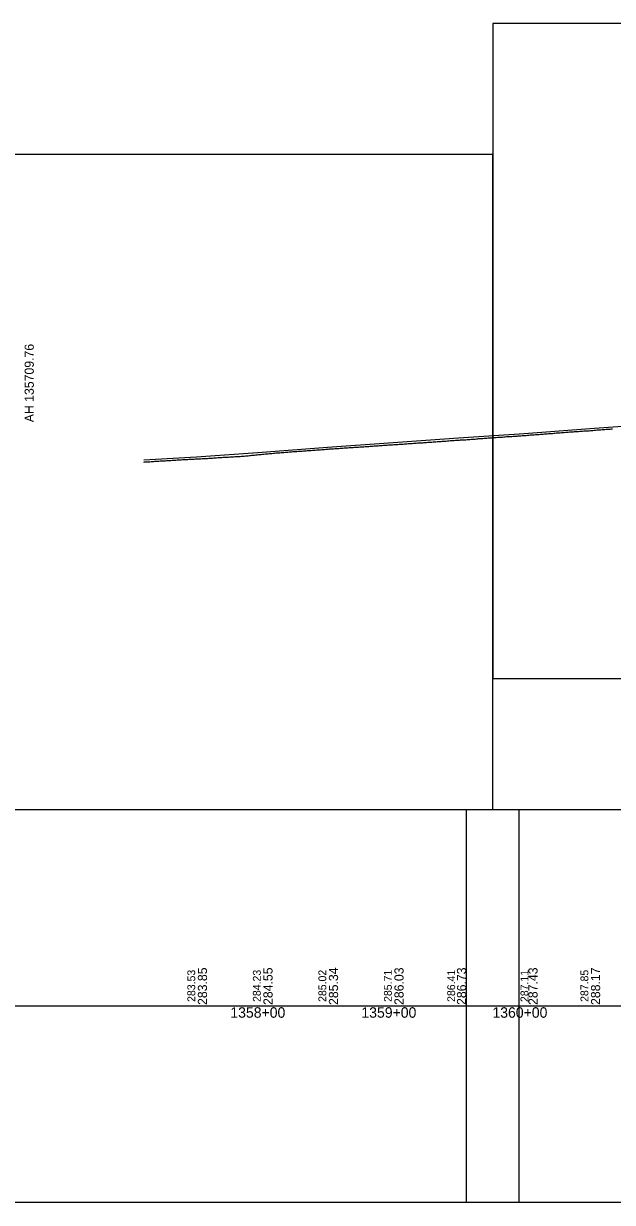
# Model space of a CAD drawing. Extents: x -3627 to 47473, y 2850 to 4350.
# Drawn here: x 23095 to 23545, y 2850 to 3750 of the extents above; entities that cross this region are included whole.
import ezdxf

# ---------------------------------------------------------------- set-up
doc = ezdxf.new("R2010")
doc.units = 0
for name, color, linetype in [('RD_DDB_Profile_EX', 7, 'Continuous'), ('RD_DDB_Profile_PR', 7, 'Continuous'), ('RD_DDB_StaTX', 7, 'Continuous'), ('RD_DDB_StripGrade', 7, 'Continuous'), ('RD_GPK_Profile_Cell', 7, 'Continuous'), ('RD_SHT_ShtClip', 7, 'Continuous')]:
    doc.layers.add(name, color=color, linetype=linetype)

msp = doc.modelspace()

# ---------------------------------------------------------------- linework, layer by layer
at = {"layer": 'RD_DDB_Profile_EX'}
for points in [[(23486.870699, 3436.29383), (23487.872155, 3436.33528), (23488.871967, 3436.376475), (23489.866682, 3436.46569), (23490.872592, 3436.56458), (23491.873491, 3436.605095), (23492.86821, 3436.66492), (23493.869666, 3436.756335), (23494.869485, 3436.807275), (23495.870948, 3436.918235), (23496.871194, 3436.97517), (23497.87265, 3437.09588), (23498.872472, 3437.146695), (23499.867176, 3437.23695), (23500.868632, 3437.328365), (23501.868467, 3437.43892), (23502.864233, 3437.44808), (23503.87016, 3437.537355), (23504.86999, 3437.628505), (23505.864687, 3437.6785), (23506.866143, 3437.720005), (23507.867051, 3437.837865), (23508.86851, 3437.979175), (23509.867671, 3438.03701), (23510.867508, 3438.02805), (23511.868972, 3438.202135), (23512.863653, 3438.211735), (23513.865109, 3438.32995), (23514.866565, 3438.430905), (23515.864115, 3438.459595), (23516.865575, 3438.539355), (23517.867036, 3438.590265), (23518.861705, 3438.690255), (23519.867648, 3438.789405), (23520.867505, 3438.792395), (23521.862175, 3438.811465), (23522.867055, 3438.970535), (23523.861729, 3439.010965), (23524.867662, 3438.97921), (23525.869127, 3439.141915), (23526.862195, 3439.19164), (23527.868123, 3439.309825), (23528.862804, 3439.369425), (23529.864267, 3439.41084), (23530.870198, 3439.55791), (23531.864879, 3439.5983), (23532.864732, 3439.739375), (23533.86281, 3439.77842), (23534.86428, 3439.860165), (23535.865749, 3439.91118), (23536.864887, 3439.98811), (23537.864741, 3440.088785), (23538.859421, 3440.14838), (23539.865344, 3440.257225), (23540.866815, 3440.308035), (23541.865951, 3440.41615), (23542.86742, 3440.466915), (23543.860487, 3440.516725), (23544.865339, 3440.56637)], [(23286.89401, 3422.11666), (23287.896593, 3422.19705), (23288.900758, 3422.26593), (23289.89553, 3422.32608), (23290.902513, 3422.374555), (23291.89558, 3422.464075), (23292.901433, 3422.543795), (23293.895631, 3422.653325), (23294.8971, 3422.7543), (23295.897418, 3422.791645), (23296.89715, 3422.8924), (23297.902993, 3423.00183), (23298.897201, 3423.06148), (23299.903036, 3423.13983), (23300.897852, 3423.179435), (23301.89872, 3423.269295), (23302.897906, 3423.31724), (23303.898771, 3423.3675), (23304.89796, 3423.444375), (23305.897662, 3423.55575), (23306.898015, 3423.563665), (23307.899482, 3423.67532), (23308.903514, 3423.70289), (23309.899536, 3423.762965), (23310.899222, 3423.87437), (23311.89959, 3424.00048), (23312.901057, 3424.05161), (23313.898458, 3424.12772), (23314.901111, 3424.189035), (23315.898505, 3424.236545), (23316.901165, 3424.28711), (23317.902632, 3424.366785), (23318.900023, 3424.44663), (23319.902686, 3424.49718), (23320.90007, 3424.63388), (23321.901542, 3424.67419), (23322.900117, 3424.720995), (23323.901589, 3424.772205), (23324.895862, 3424.9151), (23325.902849, 3425.002625), (23326.895916, 3425.052355), (23327.902903, 3425.184075), (23328.903732, 3425.26212), (23329.901083, 3425.3099), (23330.903783, 3425.349255), (23331.898082, 3425.398395), (23332.905071, 3425.49687), (23333.898139, 3425.5466), (23334.905129, 3425.58378), (23335.899448, 3425.671555), (23336.903277, 3425.747475), (23337.905999, 3425.809405), (23338.904586, 3425.89472), (23339.907316, 3426.029615), (23340.900385, 3426.10643), (23341.905443, 3426.100455), (23342.901723, 3426.215285), (23343.905493, 3426.302365), (23344.901791, 3426.340125), (23345.902589, 3426.401925), (23346.903387, 3426.4601), (23347.90485, 3426.54957), (23348.8992, 3426.57554), (23349.90194, 3426.614485), (23350.902739, 3426.714675), (23351.906506, 3426.76332), (23352.902811, 3426.801075), (23353.903607, 3426.901265), (23354.905065, 3426.952515), (23355.905864, 3427.014285), (23356.900218, 3427.063315), (23357.901674, 3427.11453), (23358.90313, 3427.177265), (23359.904587, 3427.26695), (23360.897657, 3427.31665), (23361.899113, 3427.417865), (23362.900569, 3427.519075), (23363.906301, 3427.568055), (23364.901291, 3427.66388), (23365.900831, 3427.741795), (23366.902292, 3427.804295), (23367.89727, 3427.88159), (23368.898723, 3427.932755), (23369.898283, 3428.033595), (23370.899743, 3428.08476), (23371.894702, 3428.1848), (23372.896156, 3428.197185), (23373.895734, 3428.275625), (23374.897195, 3428.36569), (23375.896439, 3428.41341), (23376.899139, 3428.51399), (23377.89872, 3428.56489), (23378.900181, 3428.643885), (23379.895117, 3428.66618), (23380.896571, 3428.76743), (23381.896171, 3428.796225), (23382.897632, 3428.886545), (23383.892549, 3428.914555), (23384.894003, 3429.0099), (23385.893623, 3429.0999), (23386.895084, 3429.151235)], [(23386.895084, 3429.151235), (23387.894314, 3429.21585), (23388.895773, 3429.30011), (23389.897231, 3429.35144), (23390.892535, 3429.404905), (23391.893996, 3429.484755), (23392.888868, 3429.613305), (23393.890321, 3429.686205), (23394.889986, 3429.74791), (23395.891447, 3429.78866), (23396.892908, 3429.85832), (23397.889993, 3429.91511), (23398.890295, 3429.977515), (23399.88511, 3430.037935), (23400.886564, 3430.089185), (23401.886286, 3430.18846), (23402.887746, 3430.25021), (23403.888075, 3430.30232), (23404.889541, 3430.35466), (23405.879898, 3430.43676), (23406.881352, 3430.548115), (23407.881696, 3430.60996), (23408.883154, 3430.67113), (23409.884612, 3430.68262), (23410.886071, 3430.833335), (23411.884792, 3430.90523), (23412.87951, 3430.995405), (23413.876517, 3431.018575), (23414.877975, 3431.079445), (23415.879434, 3431.142125), (23416.879833, 3431.203625), (23417.881296, 3431.29299), (23418.875963, 3431.412015), (23419.877419, 3431.53201), (23420.87783, 3431.614555), (23421.873224, 3431.667365), (23422.874687, 3431.759135), (23423.87615, 3431.810215), (23424.877613, 3431.829655), (23425.871207, 3431.911745), (23426.872668, 3432.0037), (23427.874128, 3432.05482), (23428.875589, 3432.087855), (23429.871515, 3432.141925), (23430.871487, 3432.24286), (23431.872955, 3432.29406), (23432.867505, 3432.326375), (23433.868462, 3432.38565), (23434.86757, 3432.442065), (23435.868523, 3432.560245), (23436.874529, 3432.618085), (23437.870084, 3432.62654), (23438.874582, 3432.748345), (23439.870156, 3432.788815), (23440.874635, 3432.878335), (23441.870229, 3432.99592), (23442.870168, 3433.10586), (23443.870301, 3433.15316), (23444.870229, 3433.213135), (23445.870373, 3433.269745), (23446.870289, 3433.361365), (23447.877282, 3433.45063), (23448.87035, 3433.5596), (23449.872833, 3433.6102), (23450.870411, 3433.70783), (23451.871874, 3433.75891), (23452.872045, 3433.815685), (23453.871935, 3433.93846), (23454.872117, 3433.99511), (23455.871995, 3434.0836), (23456.872189, 3434.1718), (23457.872056, 3434.203605), (23458.874564, 3434.204195), (23459.872117, 3434.31138), (23460.874633, 3434.32386), (23461.872177, 3434.478905), (23462.874701, 3434.560245), (23463.872238, 3434.62894), (23464.874769, 3434.6682), (23465.867839, 3434.738945), (23466.874837, 3434.79711), (23467.867907, 3434.85658), (23468.873822, 3434.895845), (23469.876364, 3434.986665), (23470.873883, 3435.113765), (23471.876432, 3435.075005), (23472.873944, 3435.162575), (23473.875407, 3435.29339), (23474.870132, 3435.373645), (23475.874371, 3435.39254), (23476.870205, 3435.50187), (23477.871661, 3435.5927), (23478.877561, 3435.61191), (23479.87063, 3435.721555), (23480.87209, 3435.84252), (23481.874645, 3435.933205), (23482.874449, 3435.98405), (23483.869171, 3436.0045), (23484.875076, 3436.08358), (23485.874883, 3436.224005), (23486.870699, 3436.29383)], [(23187.09, 3415.259485), (23187.600115, 3415.300215), (23188.595764, 3415.3496), (23189.601713, 3415.37409), (23190.595953, 3415.45539), (23191.603332, 3415.5215), (23192.596469, 3415.6122), (23193.60239, 3415.710105), (23194.604698, 3415.769875), (23195.604025, 3415.857415), (23196.604872, 3415.86698), (23197.605681, 3415.90472), (23198.605383, 3415.974115), (23199.604707, 3416.06159), (23200.607043, 3416.05301), (23201.60638, 3416.05896), (23202.607216, 3416.20936), (23203.608074, 3416.275265), (23204.607733, 3416.357285), (23205.608602, 3416.40424), (23206.609431, 3416.45463), (23207.610262, 3416.514535), (23208.61115, 3416.59235), (23209.611976, 3416.65235), (23210.610126, 3416.66081), (23211.612507, 3416.751915), (23212.611863, 3416.887115), (23213.612683, 3416.94726), (23214.61362, 3416.9942), (23215.614436, 3417.024855), (23216.612563, 3417.09179), (23217.614973, 3417.13254), (23218.614338, 3417.149105), (23219.615148, 3417.199445), (23220.622543, 3417.25779), (23221.61694, 3417.336695), (23222.621446, 3417.385205), (23223.617484, 3417.42441), (23224.618652, 3417.50614), (23225.616752, 3417.55355), (23226.617926, 3417.59457), (23227.6191, 3417.675535), (23228.613869, 3417.74582), (23229.618367, 3417.79438), (23230.619546, 3417.80577), (23231.615582, 3417.84503), (23232.616749, 3417.89627), (23233.621251, 3417.88466), (23234.616025, 3417.964325), (23235.617198, 3418.07582), (23236.61837, 3418.17714), (23237.616468, 3418.20483), (23238.617645, 3418.24589), (23239.618822, 3418.326935), (23240.613584, 3418.416845), (23241.613139, 3418.46819), (23242.619273, 3418.51714), (23243.614036, 3418.59694), (23244.615212, 3418.658235), (23245.614776, 3418.70913), (23246.614487, 3418.75686), (23247.616919, 3418.857475), (23248.618095, 3418.90867), (23249.611235, 3418.96843), (23250.617372, 3419.06738), (23251.618553, 3419.088375), (23252.613308, 3419.168535), (23253.612872, 3419.2194), (23254.619008, 3419.26835), (23255.613765, 3419.308295), (23256.614944, 3419.409485), (23257.614517, 3419.440405), (23258.61422, 3419.51785), (23259.615404, 3419.579225), (23260.616589, 3419.590515), (23261.609726, 3419.71019), (23262.612146, 3419.76081), (23263.61829, 3419.799715), (23264.613039, 3419.88971), (23265.612612, 3419.98068), (23266.613797, 3420.08199), (23267.6135, 3420.169555), (23268.614683, 3420.26072), (23269.614266, 3420.39172), (23270.609004, 3420.49172), (23271.615148, 3420.55055), (23272.616336, 3420.631885), (23273.609473, 3420.77137), (23274.610661, 3420.912595), (23275.616805, 3421.05157), (23276.611543, 3421.081675), (23277.611133, 3421.172735), (23278.61514, 3421.294115), (23279.900218, 3421.412065), (23280.894955, 3421.522005), (23281.899164, 3421.59042), (23282.895013, 3421.729815), (23283.899204, 3421.83836), (23284.89396, 3421.87831), (23285.900943, 3421.966395), (23286.89401, 3422.11666)]]:
    msp.add_lwpolyline(points, dxfattribs=at)
at = {"layer": 'RD_DDB_Profile_PR'}
msp.add_lwpolyline([(23187.09, 3416.824774), (23227.33, 3419.252), (23277.33, 3422.747), (23327.33, 3426.709), (23377.33, 3430.136), (23427.33, 3433.627), (23477.33, 3437.1435), (23527.33, 3440.8465), (23577.33, 3444.518), (23627.33, 3448.013), (23677.33, 3451.8315), (23727.33, 3455.54), (23777.33, 3458.9055), (23827.33, 3462.327), (23877.33, 3466.0305), (23927.33, 3469.635), (23977.33, 3473.388), (24027.33, 3476.9655), (24077.33, 3480.2905)], dxfattribs=at)
at = {"layer": 'RD_GPK_Profile_Cell'}
msp.add_line((1000, 3000), (46705.077602, 3000), dxfattribs=at)
at = {"layer": 'RD_SHT_ShtClip'}
for points in [[(23453.33, 3750), (23453.33, 3250), (24953.33, 3250), (24953.33, 3250), (24953.33, 3750), (24953.33, 3750)], [(21953.33, 3650), (21953.33, 3150), (23453.33, 3150), (23453.33, 3150), (23453.33, 3650), (23453.33, 3650)], [(21933.33, 3150), (23473.33, 3150), (23473.33, 2850), (21933.33, 2850)], [(23433.33, 3150), (24973.33, 3150), (24973.33, 2850), (23433.33, 2850)]]:
    msp.add_lwpolyline(points, close=True, dxfattribs=at)

# ---------------------------------------------------------------- texts
at = {"layer": 'RD_DDB_Profile_PR'}
msp.add_text('AH 135709.76', height=7, rotation=90, dxfattribs=at).set_placement((23103.12, 3445.624774))
at = {"layer": 'RD_DDB_StaTX'}
for s, p in [('1358+00', (23253.125471, 2991)), ('1359+00', (23353.125471, 2991)), ('1360+00', (23453.125471, 2991))]:
    msp.add_text(s, height=8, dxfattribs=at).set_placement(p)
at = {"layer": 'RD_DDB_StripGrade'}
for s, height, p in [('283.53', 6, (23226.33, 3003.073688)), ('283.85', 7, (23235.33, 3000.75)), ('284.23', 6, (23276.33, 3003.073688)), ('284.55', 7, (23285.33, 3000.75)), ('285.02', 6, (23326.33, 3003.073688)), ('285.34', 7, (23335.33, 3000.75)), ('285.71', 6, (23376.33, 3003.073688)), ('286.03', 7, (23385.33, 3000.75)), ('286.41', 6, (23424.65435, 3003.073688)), ('286.73', 7, (23433.044985, 3000.75)), ('287.11', 6, (23480.55574, 3002.967346)), ('287.43', 7, (23487.55574, 3000.75)), ('287.85', 6, (23526.33, 3003.073688)), ('288.17', 7, (23535.33, 3000.75))]:
    msp.add_text(s, height=height, rotation=90, dxfattribs=at).set_placement(p)

doc.saveas('drawing.dxf')
